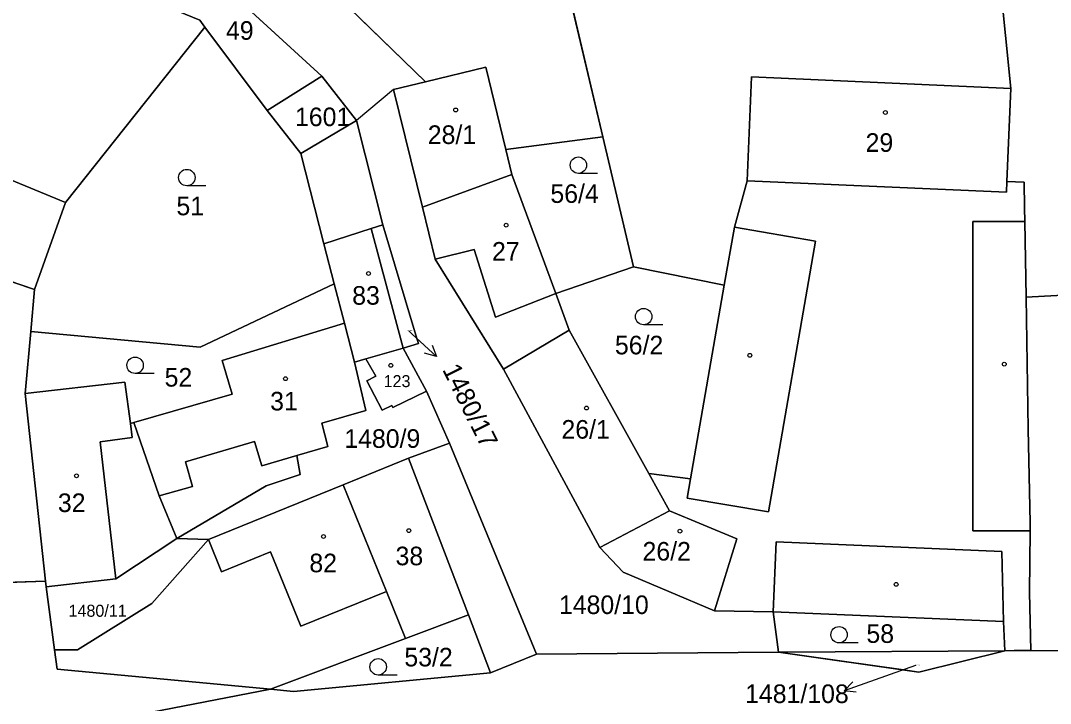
# Model space of a CAD drawing. Extents: x -760642 to -757221, y -1092371 to -1088855.
# Drawn here: x -759278.1 to -759183.9, y -1089782.4 to -1089720 of the extents above; entities that cross this region are included whole.
import ezdxf

# ---------------------------------------------------------------- set-up
doc = ezdxf.new("R2010")
doc.units = 0
for name, color, linetype in [('Vrstva 1', 7, 'Continuous'), ('Vrstva 16', 7, 'Continuous'), ('Vrstva 18', 7, 'Continuous'), ('Vrstva 19', 7, 'Continuous'), ('Vrstva 25', 7, 'Continuous'), ('Vrstva 26', 7, 'Continuous'), ('Vrstva 27', 7, 'Continuous'), ('Vrstva 4', 7, 'Continuous')]:
    doc.layers.add(name, color=color, linetype=linetype)

msp = doc.modelspace()

# ---------------------------------------------------------------- linework, layer by layer
at = {"layer": 'Vrstva 1'}
for p, q in [((-759224.83, -1089730.63), (-759230.42, -1089706.88)), ((-759257.39, -1089709.72), (-759241.06, -1089725.59)), ((-759187.48, -1089726.21), (-759188.91, -1089711.95)), ((-759260.89, -1089715.59), (-759250.54, -1089725.09)), ((-759273.98, -1089736.64), (-759261.23, -1089720.61)), ((-759261.23, -1089720.61), (-759261.71, -1089719.97)), ((-759255.54, -1089728.22), (-759261.23, -1089720.61)), ((-759241.06, -1089725.59), (-759235.52, -1089724.25)), ((-759233.69, -1089731.8), (-759235.52, -1089724.25)), ((-759255.54, -1089728.22), (-759250.54, -1089725.09)), ((-759250.54, -1089725.09), (-759247.36, -1089729.14)), ((-759211.63, -1089734.64), (-759211.21, -1089725.15)), ((-759187.48, -1089726.21), (-759211.21, -1089725.15)), ((-759243.98, -1089726.3), (-759247.36, -1089729.14)), ((-759243.98, -1089726.3), (-759241.06, -1089725.59)), ((-759241.33, -1089737.05), (-759243.98, -1089726.3)), ((-759187.86, -1089734.7), (-759187.48, -1089726.21)), ((-759252.45, -1089732.15), (-759255.54, -1089728.22)), ((-759247.36, -1089729.14), (-759244.94, -1089738.67)), ((-759224.83, -1089730.63), (-759233.69, -1089731.8)), ((-759222.03, -1089742.51), (-759224.83, -1089730.63)), ((-759233.14, -1089734.07), (-759233.69, -1089731.8)), ((-759250.34, -1089740.4), (-759252.45, -1089732.15)), ((-759280.01, -1089734.15), (-759273.98, -1089736.64)), ((-759241.33, -1089737.05), (-759233.14, -1089734.07)), ((-759229.12, -1089744.97), (-759233.14, -1089734.07)), ((-759211.63, -1089734.64), (-759212.79, -1089738.88)), ((-759187.86, -1089734.7), (-759186.26, -1089734.77)), ((-759186.26, -1089734.77), (-759186.23, -1089737.11)), ((-759273.98, -1089736.64), (-759276.83, -1089744.58)), ((-759241.33, -1089737.05), (-759240.16, -1089741.81)), ((-759186.23, -1089737.11), (-759186.21, -1089738.36)), ((-759186.21, -1089738.36), (-759186.1, -1089745.3)), ((-759246.01, -1089739.01), (-759250.34, -1089740.4)), ((-759244.94, -1089738.67), (-759246.01, -1089739.01)), ((-759243.09, -1089749.95), (-759246.01, -1089739.01)), ((-759241.7, -1089749.53), (-759244.94, -1089738.67)), ((-759213.72, -1089744.2), (-759212.79, -1089738.88)), ((-759249.4, -1089744.07), (-759250.34, -1089740.4)), ((-759240.16, -1089741.81), (-759233.92, -1089751.86)), ((-759229.12, -1089744.97), (-759222.03, -1089742.51)), ((-759222.03, -1089742.51), (-759213.72, -1089744.2)), ((-759261.67, -1089749.86), (-759249.4, -1089744.07)), ((-759248.47, -1089747.68), (-759249.4, -1089744.07)), ((-759216.8, -1089761.89), (-759213.72, -1089744.2)), ((-759186.1, -1089745.3), (-759164.68, -1089744.12)), ((-759277.17, -1089748.44), (-759276.83, -1089744.58)), ((-759227.89, -1089748.3), (-759229.12, -1089744.97)), ((-759186.1, -1089745.3), (-759185.92, -1089757.37)), ((-759248.47, -1089747.68), (-759259.65, -1089751.08)), ((-759247.56, -1089751.24), (-759248.47, -1089747.68)), ((-759277.67, -1089754.1), (-759277.17, -1089748.44)), ((-759277.17, -1089748.44), (-759261.67, -1089749.86)), ((-759227.89, -1089748.3), (-759233.92, -1089751.86)), ((-759227.89, -1089748.3), (-759220.61, -1089761.42)), ((-759243.09, -1089749.95), (-759241.7, -1089749.53)), ((-759243.09, -1089749.95), (-759246.5, -1089750.94)), ((-759240.96, -1089753.9), (-759243.09, -1089749.95)), ((-759259.65, -1089751.08), (-759258.74, -1089754.16)), ((-759246.5, -1089750.94), (-759247.56, -1089751.24)), ((-759246.5, -1089755.67), (-759247.56, -1089751.24)), ((-759246.5, -1089750.94), (-759245.61, -1089752.53)), ((-759245.61, -1089752.53), (-759246.41, -1089752.94)), ((-759225.1, -1089768.17), (-759233.92, -1089751.86)), ((-759268.57, -1089753.07), (-759277.67, -1089754.1)), ((-759268.57, -1089753.07), (-759268.05, -1089756.85)), ((-759246.41, -1089752.94), (-759245.01, -1089755.61)), ((-759277.67, -1089754.1), (-759275.82, -1089771.26)), ((-759267.74, -1089756.76), (-759258.74, -1089754.16)), ((-759244.03, -1089755.39), (-759240.96, -1089753.9)), ((-759240.96, -1089753.9), (-759238.86, -1089758.63)), ((-759245.01, -1089755.61), (-759244.12, -1089755.21)), ((-759244.12, -1089755.21), (-759244.03, -1089755.39)), ((-759246.5, -1089755.67), (-759250.55, -1089756.81)), ((-759267.74, -1089756.76), (-759268.05, -1089756.85)), ((-759265.41, -1089763.46), (-759267.74, -1089756.76)), ((-759250.55, -1089756.81), (-759250, -1089758.96)), ((-759185.92, -1089757.37), (-759185.72, -1089765.93)), ((-759250, -1089758.96), (-759252.81, -1089759.78)), ((-759238.86, -1089758.63), (-759242.62, -1089760.02)), ((-759238.86, -1089758.63), (-759230.9, -1089777.93)), ((-759252.52, -1089761.52), (-759252.81, -1089759.78)), ((-759242.62, -1089760.02), (-759248.59, -1089762.45)), ((-759255.63, -1089762.56), (-759252.52, -1089761.52)), ((-759216.8, -1089761.89), (-759220.61, -1089761.42)), ((-759220.61, -1089761.42), (-759218.72, -1089764.82)), ((-759263.8, -1089767.36), (-759255.63, -1089762.56)), ((-759248.59, -1089762.45), (-759260.92, -1089767.45)), ((-759248.59, -1089762.45), (-759244.63, -1089772.22)), ((-759265.41, -1089763.46), (-759263.8, -1089767.36)), ((-759218.72, -1089764.82), (-759225.1, -1089768.17)), ((-759218.72, -1089764.82), (-759212.55, -1089767.39)), ((-759185.73, -1089766.66), (-759185.79, -1089772.31)), ((-759185.72, -1089765.93), (-759185.73, -1089766.66)), ((-759269.39, -1089771.05), (-759263.8, -1089767.36)), ((-759260.92, -1089767.45), (-759266.09, -1089773.31)), ((-759263.8, -1089767.36), (-759260.92, -1089767.45)), ((-759214.61, -1089773.98), (-759212.55, -1089767.39)), ((-759222.96, -1089770.44), (-759225.1, -1089768.17)), ((-759222.96, -1089770.44), (-759214.61, -1089773.98)), ((-759282.31, -1089771.47), (-759275.82, -1089771.26)), ((-759275.82, -1089771.26), (-759275.76, -1089771.78)), ((-759269.39, -1089771.05), (-759275.76, -1089771.78)), ((-759275.76, -1089771.78), (-759274.99, -1089777.55)), ((-759244.63, -1089772.22), (-759242.89, -1089776.5)), ((-759185.79, -1089772.31), (-759185.67, -1089777.61)), ((-759266.09, -1089773.31), (-759272.89, -1089777.55)), ((-759242.89, -1089776.5), (-759237.13, -1089774.33)), ((-759237.13, -1089774.33), (-759235.09, -1089779.66)), ((-759214.61, -1089773.98), (-759209.24, -1089774.06)), ((-759188.16, -1089774.95), (-759209.24, -1089774.06)), ((-759209.24, -1089774.06), (-759208.76, -1089777.77)), ((-759188.16, -1089774.95), (-759188.03, -1089777.62)), ((-759242.89, -1089776.5), (-759255.22, -1089781.14)), ((-759272.89, -1089777.55), (-759274.99, -1089777.55)), ((-759274.99, -1089777.55), (-759274.75, -1089779.3)), ((-759230.9, -1089777.93), (-759235.09, -1089779.66)), ((-759208.76, -1089777.77), (-759230.9, -1089777.93)), ((-759188.03, -1089777.62), (-759208.76, -1089777.77)), ((-759208.76, -1089777.77), (-759195.92, -1089779.58)), ((-759195.92, -1089779.58), (-759188.03, -1089777.62)), ((-759187.18, -1089777.61), (-759188.03, -1089777.62)), ((-759187.18, -1089777.61), (-759185.67, -1089777.61)), ((-759185.67, -1089777.61), (-759163.35, -1089777.67)), ((-759274.75, -1089779.3), (-759255.22, -1089781.14)), ((-759253.14, -1089781.34), (-759235.09, -1089779.66)), ((-759255.22, -1089781.14), (-759267.19, -1089783.47)), ((-759255.22, -1089781.14), (-759253.14, -1089781.34))]:
    msp.add_line(p, q, dxfattribs=at)
at = {"layer": 'Vrstva 16'}
for p, q in [((-759242.58, -1089748.38), (-759242.26, -1089748.68)), ((-759242.26, -1089748.68), (-759240.053, -1089750.712)), ((-759196.21, -1089778.99), (-759199.91, -1089780.29)), ((-759199.91, -1089780.29), (-759202.74, -1089781.287))]:
    msp.add_line(p, q, dxfattribs=at)
for points in [[(-759240.45, -1089749.667), (-759240.053, -1089750.712), (-759241.128, -1089750.403)], [(-759201.63, -1089781.426), (-759202.74, -1089781.287), (-759201.963, -1089780.483)]]:
    msp.add_lwpolyline(points, dxfattribs=at)
at = {"layer": 'Vrstva 25'}
for p, q in [((-759225.31, -1089733.97), (-759227.06, -1089733.97)), ((-759261.14, -1089735.1), (-759262.89, -1089735.1)), ((-759219.34, -1089747.82), (-759221.09, -1089747.82)), ((-759265.87, -1089752.27), (-759267.62, -1089752.27)), ((-759201.46, -1089776.91), (-759203.21, -1089776.91)), ((-759243.63, -1089779.85), (-759245.38, -1089779.85))]:
    msp.add_line(p, q, dxfattribs=at)
for centre, radius in [((-759238.29, -1089728.17), 0.175), ((-759198.97, -1089728.4), 0.175), ((-759227.06, -1089733.22), 0.75), ((-759262.89, -1089734.35), 0.75), ((-759233.67, -1089738.71), 0.175), ((-759246.26, -1089743.12), 0.175), ((-759221.09, -1089747.07), 0.75), ((-759267.62, -1089751.52), 0.75), ((-759211.37, -1089750.61), 0.175), ((-759244.22, -1089751.53), 0.175), ((-759188.09, -1089751.42), 0.175), ((-759253.86, -1089752.75), 0.175), ((-759226.32, -1089755.43), 0.175), ((-759272.98, -1089761.63), 0.175), ((-759242.58, -1089766.64), 0.175), ((-759217.77, -1089766.69), 0.175), ((-759250.38, -1089767.18), 0.175), ((-759197.98, -1089771.56), 0.175), ((-759203.21, -1089776.16), 0.75), ((-759245.38, -1089779.1), 0.75)]:
    msp.add_circle(centre, radius, dxfattribs=at)
at = {"layer": 'Vrstva 26'}
for points in [[(-759186.23, -1089737.11), (-759186.21, -1089738.36), (-759186.1, -1089745.3), (-759164.68, -1089744.12), (-759164.62, -1089743.18), (-759162.99, -1089731.01), (-759161.57, -1089695.06), (-759184.67, -1089688.55), (-759190.55, -1089701.69), (-759190.4, -1089702.66), (-759188.91, -1089711.95), (-759187.48, -1089726.21), (-759187.86, -1089734.7), (-759186.26, -1089734.77), (-759186.23, -1089737.11)], [(-759280.01, -1089734.15), (-759273.98, -1089736.64), (-759261.23, -1089720.61), (-759261.71, -1089719.97), (-759266.25, -1089718.07), (-759276.5, -1089708.25), (-759288.15, -1089693.62), (-759297.08, -1089688.73), (-759300.26, -1089705.68), (-759303.27, -1089717.63), (-759303.25, -1089723.2), (-759283.81, -1089722.53), (-759283.35, -1089731.84), (-759280.01, -1089734.15)], [(-759212.79, -1089738.88), (-759211.63, -1089734.64), (-759211.21, -1089725.15), (-759187.48, -1089726.21), (-759188.91, -1089711.95), (-759190.4, -1089702.66), (-759230.42, -1089706.88), (-759224.83, -1089730.63), (-759222.03, -1089742.51), (-759213.72, -1089744.2), (-759212.79, -1089738.88)], [(-759224.83, -1089730.63), (-759230.42, -1089706.88), (-759257.39, -1089709.72), (-759241.06, -1089725.59), (-759235.52, -1089724.25), (-759233.69, -1089731.8), (-759224.83, -1089730.63)], [(-759266.25, -1089718.07), (-759261.71, -1089719.97), (-759261.23, -1089720.61), (-759255.54, -1089728.22), (-759250.54, -1089725.09), (-759260.89, -1089715.59), (-759265.45, -1089711.4), (-759266.25, -1089718.07)], [(-759255.54, -1089728.22), (-759261.23, -1089720.61), (-759273.98, -1089736.64), (-759276.83, -1089744.58), (-759277.17, -1089748.44), (-759261.67, -1089749.86), (-759249.4, -1089744.07), (-759250.34, -1089740.4), (-759252.45, -1089732.15), (-759255.54, -1089728.22)], [(-759233.69, -1089731.8), (-759235.52, -1089724.25), (-759241.06, -1089725.59), (-759243.98, -1089726.3), (-759241.33, -1089737.05), (-759233.14, -1089734.07), (-759233.69, -1089731.8)], [(-759250.54, -1089725.09), (-759255.54, -1089728.22), (-759252.45, -1089732.15), (-759247.36, -1089729.14), (-759250.54, -1089725.09)], [(-759187.9, -1089735.7), (-759187.86, -1089734.7), (-759187.48, -1089726.21), (-759211.21, -1089725.15), (-759211.63, -1089734.64), (-759187.9, -1089735.7)], [(-759241.838, -1089749.069), (-759241.7, -1089749.53), (-759243.09, -1089749.95), (-759240.96, -1089753.9), (-759238.86, -1089758.63), (-759230.9, -1089777.93), (-759208.76, -1089777.77), (-759209.24, -1089774.06), (-759214.61, -1089773.98), (-759222.96, -1089770.44), (-759225.1, -1089768.17), (-759233.92, -1089751.86), (-759240.16, -1089741.81), (-759241.33, -1089737.05), (-759243.98, -1089726.3), (-759247.36, -1089729.14), (-759244.94, -1089738.67), (-759241.838, -1089749.069)], [(-759247.36, -1089729.14), (-759252.45, -1089732.15), (-759250.34, -1089740.4), (-759246.01, -1089739.01), (-759244.94, -1089738.67), (-759247.36, -1089729.14)], [(-759229.12, -1089744.97), (-759222.03, -1089742.51), (-759224.83, -1089730.63), (-759233.69, -1089731.8), (-759233.14, -1089734.07), (-759229.12, -1089744.97)], [(-759283.35, -1089731.84), (-759296.11, -1089732.77), (-759295.66, -1089747.93), (-759304.09, -1089748.18), (-759303.95, -1089743.71), (-759305.7, -1089743.76), (-759304.85, -1089750.31), (-759303.6, -1089750.09), (-759290.87, -1089755.11), (-759282.77, -1089754.95), (-759282.62, -1089760.32), (-759282.06, -1089760.32), (-759282.03, -1089766.06), (-759282.46, -1089766.07), (-759283.62, -1089766.09), (-759283.53, -1089771.51), (-759282.31, -1089771.47), (-759275.82, -1089771.26), (-759277.67, -1089754.1), (-759277.17, -1089748.44), (-759276.83, -1089744.58), (-759282.82, -1089742.58), (-759280.01, -1089734.15), (-759283.35, -1089731.84)], [(-759282.82, -1089742.58), (-759276.83, -1089744.58), (-759273.98, -1089736.64), (-759280.01, -1089734.15), (-759282.82, -1089742.58)], [(-759236.59, -1089740.93), (-759234.65, -1089747.12), (-759229.12, -1089744.97), (-759233.14, -1089734.07), (-759241.33, -1089737.05), (-759240.16, -1089741.81), (-759236.59, -1089740.93)], [(-759185.73, -1089766.66), (-759190.98, -1089766.66), (-759190.98, -1089738.36), (-759186.21, -1089738.36), (-759186.23, -1089737.11), (-759186.26, -1089734.77), (-759187.86, -1089734.7), (-759187.9, -1089735.7), (-759211.63, -1089734.64), (-759212.79, -1089738.88), (-759205.36, -1089740.18), (-759209.67, -1089764.92), (-759217.11, -1089763.66), (-759216.8, -1089761.89), (-759220.61, -1089761.42), (-759218.72, -1089764.82), (-759212.55, -1089767.39), (-759214.61, -1089773.98), (-759209.24, -1089774.06), (-759208.97, -1089767.67), (-759188.3, -1089768.55), (-759188.16, -1089774.95), (-759188.03, -1089777.62), (-759187.18, -1089777.61), (-759185.67, -1089777.61), (-759185.79, -1089772.31), (-759185.73, -1089766.66)], [(-759185.73, -1089766.66), (-759185.72, -1089765.93), (-759185.92, -1089757.37), (-759186.1, -1089745.3), (-759186.21, -1089738.36), (-759190.98, -1089738.36), (-759190.98, -1089766.66), (-759185.73, -1089766.66)], [(-759248.47, -1089747.68), (-759247.56, -1089751.24), (-759246.5, -1089750.94), (-759243.09, -1089749.95), (-759246.01, -1089739.01), (-759250.34, -1089740.4), (-759249.4, -1089744.07), (-759248.47, -1089747.68)], [(-759241.838, -1089749.069), (-759244.94, -1089738.67), (-759246.01, -1089739.01), (-759243.09, -1089749.95), (-759241.7, -1089749.53), (-759241.838, -1089749.069)], [(-759205.36, -1089740.18), (-759212.79, -1089738.88), (-759213.72, -1089744.2), (-759216.8, -1089761.89), (-759217.11, -1089763.66), (-759209.67, -1089764.92), (-759205.36, -1089740.18)], [(-759229.12, -1089744.97), (-759234.65, -1089747.12), (-759236.59, -1089740.93), (-759240.16, -1089741.81), (-759233.92, -1089751.86), (-759227.89, -1089748.3), (-759229.12, -1089744.97)], [(-759220.61, -1089761.42), (-759216.8, -1089761.89), (-759213.72, -1089744.2), (-759222.03, -1089742.51), (-759229.12, -1089744.97), (-759227.89, -1089748.3), (-759220.61, -1089761.42)], [(-759277.17, -1089748.44), (-759277.67, -1089754.1), (-759268.57, -1089753.07), (-759268.05, -1089756.85), (-759267.74, -1089756.76), (-759258.74, -1089754.16), (-759259.65, -1089751.08), (-759248.47, -1089747.68), (-759249.4, -1089744.07), (-759261.67, -1089749.86), (-759277.17, -1089748.44)], [(-759160.1, -1089752.53), (-759162.27, -1089769.31), (-759158.55, -1089769.51), (-759156.8, -1089752.52), (-759165, -1089749.51), (-759164.68, -1089744.12), (-759186.1, -1089745.3), (-759185.92, -1089757.37), (-759185.72, -1089765.93), (-759185.73, -1089766.66), (-759185.79, -1089772.31), (-759185.67, -1089777.61), (-759163.35, -1089777.67), (-759170.81, -1089776.7), (-759167.54, -1089751.56), (-759160.1, -1089752.53)], [(-759256.04, -1089760.72), (-759252.81, -1089759.78), (-759250, -1089758.96), (-759250.55, -1089756.81), (-759246.5, -1089755.67), (-759247.56, -1089751.24), (-759248.47, -1089747.68), (-759259.65, -1089751.08), (-759258.74, -1089754.16), (-759267.74, -1089756.76), (-759265.41, -1089763.46), (-759262.37, -1089762.6), (-759263.02, -1089760.34), (-759256.69, -1089758.48), (-759256.04, -1089760.72)], [(-759225.1, -1089768.17), (-759218.72, -1089764.82), (-759220.61, -1089761.42), (-759227.89, -1089748.3), (-759233.92, -1089751.86), (-759225.1, -1089768.17)], [(-759243.09, -1089749.95), (-759246.5, -1089750.94), (-759245.61, -1089752.53), (-759246.41, -1089752.94), (-759245.01, -1089755.61), (-759244.12, -1089755.21), (-759244.03, -1089755.39), (-759240.96, -1089753.9), (-759243.09, -1089749.95)], [(-759244.12, -1089755.21), (-759245.01, -1089755.61), (-759246.41, -1089752.94), (-759245.61, -1089752.53), (-759246.5, -1089750.94), (-759247.56, -1089751.24), (-759246.5, -1089755.67), (-759250.55, -1089756.81), (-759250, -1089758.96), (-759252.81, -1089759.78), (-759252.52, -1089761.52), (-759255.63, -1089762.56), (-759263.8, -1089767.36), (-759260.92, -1089767.45), (-759248.59, -1089762.45), (-759242.62, -1089760.02), (-759238.86, -1089758.63), (-759240.96, -1089753.9), (-759244.03, -1089755.39), (-759244.12, -1089755.21)], [(-759267.88, -1089758.13), (-759268.05, -1089756.85), (-759268.57, -1089753.07), (-759277.67, -1089754.1), (-759275.82, -1089771.26), (-759275.76, -1089771.78), (-759269.39, -1089771.05), (-759270.82, -1089758.53), (-759267.88, -1089758.13)], [(-759270.82, -1089758.53), (-759269.39, -1089771.05), (-759263.8, -1089767.36), (-759265.41, -1089763.46), (-759267.74, -1089756.76), (-759268.05, -1089756.85), (-759267.88, -1089758.13), (-759270.82, -1089758.53)], [(-759256.04, -1089760.72), (-759256.69, -1089758.48), (-759263.02, -1089760.34), (-759262.37, -1089762.6), (-759265.41, -1089763.46), (-759263.8, -1089767.36), (-759255.63, -1089762.56), (-759252.52, -1089761.52), (-759252.81, -1089759.78), (-759256.04, -1089760.72)], [(-759242.62, -1089760.02), (-759237.13, -1089774.33), (-759235.09, -1089779.66), (-759230.9, -1089777.93), (-759238.86, -1089758.63), (-759242.62, -1089760.02)], [(-759237.13, -1089774.33), (-759242.62, -1089760.02), (-759248.59, -1089762.45), (-759244.63, -1089772.22), (-759242.89, -1089776.5), (-759237.13, -1089774.33)], [(-759252.46, -1089775.39), (-759244.63, -1089772.22), (-759248.59, -1089762.45), (-759260.92, -1089767.45), (-759259.72, -1089770.42), (-759255.22, -1089768.59), (-759252.46, -1089775.39)], [(-759218.72, -1089764.82), (-759225.1, -1089768.17), (-759222.96, -1089770.44), (-759214.61, -1089773.98), (-759212.55, -1089767.39), (-759218.72, -1089764.82)], [(-759260.92, -1089767.45), (-759263.8, -1089767.36), (-759269.39, -1089771.05), (-759275.76, -1089771.78), (-759274.99, -1089777.55), (-759272.89, -1089777.55), (-759266.09, -1089773.31), (-759260.92, -1089767.45)], [(-759252.46, -1089775.39), (-759255.22, -1089768.59), (-759259.72, -1089770.42), (-759260.92, -1089767.45), (-759266.09, -1089773.31), (-759272.89, -1089777.55), (-759274.99, -1089777.55), (-759274.75, -1089779.3), (-759255.22, -1089781.14), (-759242.89, -1089776.5), (-759244.63, -1089772.22), (-759252.46, -1089775.39)], [(-759188.3, -1089768.55), (-759208.97, -1089767.67), (-759209.24, -1089774.06), (-759188.16, -1089774.95), (-759188.3, -1089768.55)], [(-759279.06, -1089785.04), (-759267.19, -1089783.47), (-759255.22, -1089781.14), (-759274.75, -1089779.3), (-759274.99, -1089777.55), (-759275.76, -1089771.78), (-759275.82, -1089771.26), (-759282.31, -1089771.47)], [(-759242.89, -1089776.5), (-759255.22, -1089781.14), (-759253.14, -1089781.34), (-759235.09, -1089779.66), (-759237.13, -1089774.33), (-759242.89, -1089776.5)], [(-759188.03, -1089777.62), (-759188.16, -1089774.95), (-759209.24, -1089774.06), (-759208.76, -1089777.77), (-759188.03, -1089777.62)], [(-759147.975, -1089779.722), (-759154.89, -1089778.9), (-759163.35, -1089777.67), (-759185.67, -1089777.61), (-759187.18, -1089777.61), (-759188.03, -1089777.62), (-759195.92, -1089779.58), (-759197.325, -1089779.382), (-759208.76, -1089777.77), (-759230.9, -1089777.93), (-759235.09, -1089779.66), (-759253.14, -1089781.34), (-759255.22, -1089781.14), (-759267.19, -1089783.47), (-759279.06, -1089785.04)], [(-759197.325, -1089779.382), (-759195.92, -1089779.58), (-759188.03, -1089777.62), (-759208.76, -1089777.77), (-759197.325, -1089779.382)]]:
    msp.add_lwpolyline(points, dxfattribs=at)
at = {"layer": 'Vrstva 27'}
msp.add_lwpolyline([(-759284.95, -1089676.99), (-759263.55, -1089703.73), (-759257.39, -1089709.72), (-759241.06, -1089725.59), (-759243.98, -1089726.3), (-759247.36, -1089729.14), (-759250.54, -1089725.09), (-759260.89, -1089715.59), (-759265.45, -1089711.4), (-759273.69, -1089700.21), (-759288.15, -1089693.62)], dxfattribs=at)
at = {"layer": 'Vrstva 4'}
for p, q in [((-759252.45, -1089732.15), (-759247.36, -1089729.14)), ((-759187.9, -1089735.7), (-759211.63, -1089734.64)), ((-759187.9, -1089735.7), (-759187.86, -1089734.7)), ((-759190.98, -1089766.66), (-759190.98, -1089738.36)), ((-759190.98, -1089738.36), (-759186.21, -1089738.36)), ((-759212.79, -1089738.88), (-759205.36, -1089740.18)), ((-759209.67, -1089764.92), (-759205.36, -1089740.18)), ((-759236.59, -1089740.93), (-759240.16, -1089741.81)), ((-759234.65, -1089747.12), (-759236.59, -1089740.93)), ((-759276.83, -1089744.58), (-759282.82, -1089742.58)), ((-759234.65, -1089747.12), (-759229.12, -1089744.97)), ((-759268.05, -1089756.85), (-759267.88, -1089758.13)), ((-759267.88, -1089758.13), (-759270.82, -1089758.53)), ((-759270.82, -1089758.53), (-759269.39, -1089771.05)), ((-759256.69, -1089758.48), (-759263.02, -1089760.34)), ((-759256.04, -1089760.72), (-759256.69, -1089758.48)), ((-759252.81, -1089759.78), (-759256.04, -1089760.72)), ((-759242.62, -1089760.02), (-759237.13, -1089774.33)), ((-759263.02, -1089760.34), (-759262.37, -1089762.6)), ((-759217.11, -1089763.66), (-759216.8, -1089761.89)), ((-759262.37, -1089762.6), (-759265.41, -1089763.46)), ((-759209.67, -1089764.92), (-759217.11, -1089763.66)), ((-759185.73, -1089766.66), (-759190.98, -1089766.66)), ((-759259.72, -1089770.42), (-759260.92, -1089767.45)), ((-759208.97, -1089767.67), (-759209.24, -1089774.06)), ((-759208.97, -1089767.67), (-759188.3, -1089768.55)), ((-759255.22, -1089768.59), (-759259.72, -1089770.42)), ((-759252.46, -1089775.39), (-759255.22, -1089768.59)), ((-759188.16, -1089774.95), (-759188.3, -1089768.55)), ((-759244.63, -1089772.22), (-759252.46, -1089775.39))]:
    msp.add_line(p, q, dxfattribs=at)

# ---------------------------------------------------------------- texts
at = {"layer": 'Vrstva 16'}
msp.add_text('1480/17', height=1.7, rotation=296.50131, dxfattribs=at).set_placement((-759239.541, -1089751.909))
msp.add_text('1481/108', height=1.7, dxfattribs=at).set_placement((-759211.805, -1089782.41))
at = {"layer": 'Vrstva 18'}
for s, height, p in [('49', 1.7, (-759259.306, -1089721.75)), ('1601', 1.7, (-759252.992, -1089729.65)), ('56/4', 1.7, (-759229.622, -1089736.67)), ('51', 1.7, (-759263.84, -1089737.8)), ('1480/17', 0.1, (-759242.75, -1089748.38)), ('56/2', 1.7, (-759223.717, -1089750.52)), ('52', 1.7, (-759264.922, -1089753.47)), ('1480/9', 1.7, (-759248.478, -1089759.07)), ('1480/10', 1.7, (-759228.84, -1089774.27)), ('1480/11', 1.1, (-759273.71, -1089774.52)), ('58', 1.7, (-759200.705, -1089776.91)), ('53/2', 1.7, (-759242.984, -1089779.06)), ('1481/108', 0.1, (-759196.396, -1089778.99))]:
    msp.add_text(s, height=height, dxfattribs=at).set_placement(p)
at = {"layer": 'Vrstva 19'}
for s, height, p in [('28/1', 1.7, (-759240.842, -1089731.28)), ('29', 1.7, (-759200.781, -1089732)), ('27', 1.7, (-759234.966, -1089741.95)), ('83', 1.7, (-759247.756, -1089745.98)), ('123', 1.1, (-759244.88, -1089753.52)), ('31', 1.7, (-759255.266, -1089755.65)), ('26/1', 1.7, (-759228.609, -1089758.23)), ('32', 1.7, (-759274.688, -1089764.94)), ('26/2', 1.7, (-759221.191, -1089769.38)), ('82', 1.7, (-759251.674, -1089770.45)), ('38', 1.7, (-759243.79, -1089769.81))]:
    msp.add_text(s, height=height, dxfattribs=at).set_placement(p)

doc.saveas('drawing.dxf')
